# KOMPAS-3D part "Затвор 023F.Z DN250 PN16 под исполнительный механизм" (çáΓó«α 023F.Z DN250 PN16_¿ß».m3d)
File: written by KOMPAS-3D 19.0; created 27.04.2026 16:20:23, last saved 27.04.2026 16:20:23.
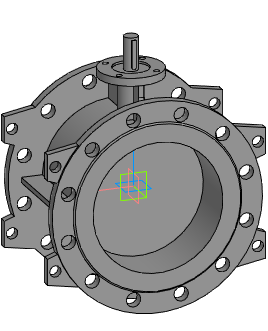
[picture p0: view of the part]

Document properties: Автор: Евгений; Полное имя файла: Z:\3.Личные\kachalov\3d для проектировщиков\1.7 Тип 023F.Z Затвор дисковый поворотный фланцевый с двумя эксцентриками\Затвор 023F.Z DN200-DN1600_исп\_stp_Затвор 023F.Z DN200-DN1600_исп\Затвор 023F.Z DN250 PN16_исп.m3d

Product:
- Part/product: Затвор 023F.Z DN250 PN16 под исполнительный механизм

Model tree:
1. Операция без истории:1  (labels: Затвор 023F.Z DN250 PN16 под исполнительный механизм)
